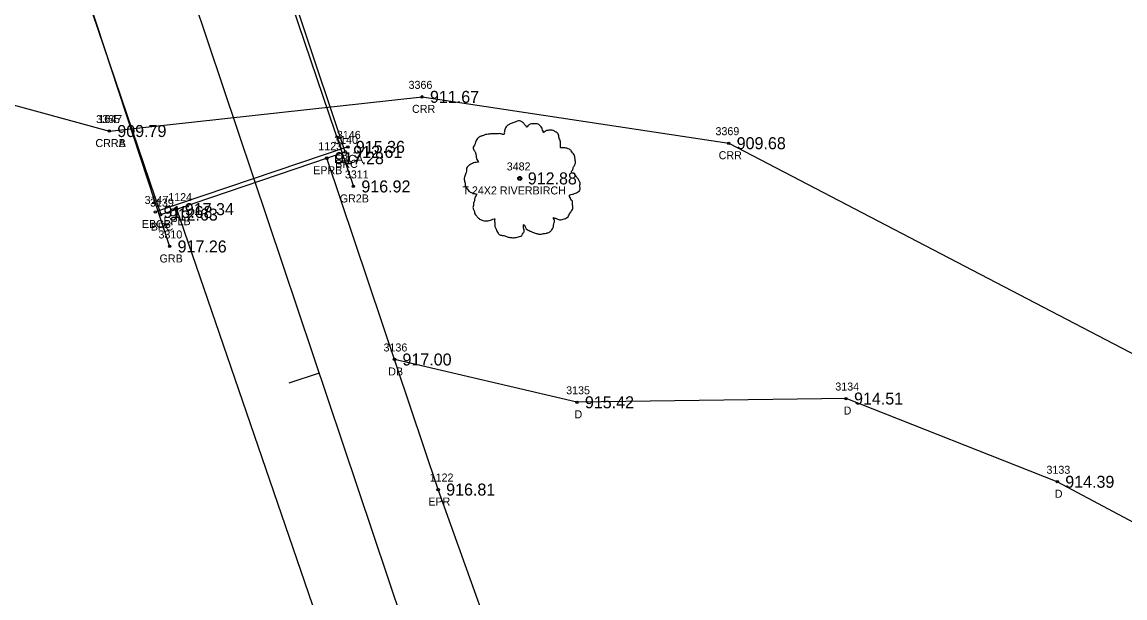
# Model space of a CAD drawing. Extents: x 1528109 to 1531398, y 1157799 to 1162548.
# Drawn here: x 1529638.1 to 1529775.9, y 1160168.9 to 1160240.8 of the extents above; entities that cross this region are included whole.
import ezdxf

# ---------------------------------------------------------------- set-up
doc = ezdxf.new("R2010")
doc.units = 0
for name, color, linetype in [('RD_EX_Bridge', 7, 'Continuous'), ('RD_EX_Bridge_txCode', 7, 'Continuous'), ('RD_EX_Driveway', 7, 'Continuous'), ('RD_EX_Driveway_txCode', 7, 'Continuous'), ('RD_EX_GuardRail', 7, 'Continuous'), ('RD_EX_GuardRail_txCode', 7, 'Continuous'), ('RD_EX_H2O', 7, 'Continuous'), ('RD_EX_H2O_txCode', 7, 'Continuous'), ('RD_EX_Road', 7, 'Continuous'), ('RD_EX_Road_txCode', 7, 'Continuous'), ('RD_EX_TX_Bridge_ELEV', 7, 'Continuous'), ('RD_EX_TX_Driveway_ELEV', 7, 'Continuous'), ('RD_EX_TX_GuardRail_ELEV', 7, 'Continuous'), ('RD_EX_TX_H2O_ELEV', 7, 'Continuous'), ('RD_EX_TX_Road_ELEV', 7, 'Continuous'), ('RD_EX_TX_VEG_ELEV', 7, 'Continuous'), ('RD_EX_VEG', 7, 'Continuous'), ('RD_EX_VEG_txCode', 7, 'Continuous'), ('RD_HC_Cl', 7, 'Continuous'), ('RD_HC_Data_Tic', 7, 'Continuous'), ('RD_SMD_Locator', 7, 'Continuous')]:
    doc.layers.add(name, color=color, linetype=linetype)

msp = doc.modelspace()

# ---------------------------------------------------------------- linework, layer by layer
at = {"layer": 'RD_EX_Bridge'}
msp.add_line((1529678.82, 1160225.23), (1529654.77, 1160217.1), dxfattribs=at)
msp.add_lwpolyline([(1529640.55, 1160338.19), (1529616.81, 1160330.27), (1529655.43, 1160216.77), (1529678.49, 1160224.61), (1529640.55, 1160338.19)], dxfattribs=at)
at = {"layer": 'RD_EX_Driveway'}
msp.add_lwpolyline([(1529846.69, 1160141.22), (1529808.38, 1160161.6), (1529767.49, 1160183.39), (1529741.09, 1160193.79), (1529707.45, 1160193.32), (1529684.65, 1160198.67)], dxfattribs=at)
at = {"layer": 'RD_EX_GuardRail'}
for points in [[(1529639.21, 1160341.22), (1529658.79, 1160281.43), (1529679.51, 1160220.29)], [(1529616.58, 1160333.92), (1529636.5, 1160273.84), (1529656.54, 1160212.79)]]:
    msp.add_lwpolyline(points, dxfattribs=at)
at = {"layer": 'RD_EX_H2O'}
for points in [[(1529355.46, 1160373.84), (1529380.28, 1160350.91), (1529399.96, 1160333.39), (1529434.31, 1160284.33), (1529465.42, 1160247.15), (1529516.1, 1160225.51), (1529574.64, 1160230.43), (1529629.96, 1160232.41), (1529649.01, 1160227.21)], [(1529649.01, 1160227.21), (1529688.09, 1160231.48), (1529726.42, 1160225.69), (1529778.48, 1160198.58), (1529816.5, 1160172.95), (1529890.76, 1160164.82), (1530012.06, 1160143.92), (1530047.21, 1160111.79), (1530065, 1160080.23), (1530106.89, 1160040.72)]]:
    msp.add_lwpolyline(points, dxfattribs=at)
at = {"layer": 'RD_EX_Road'}
for points in [[(1529774.72, 1159933.62), (1529755.68, 1159989.25), (1529731.24, 1160061.98), (1529709.49, 1160126.43), (1529696.87, 1160163.6), (1529690.11, 1160182.42), (1529676.19, 1160223.82)], [(1529755.29, 1159927.01), (1529736.93, 1159982.35), (1529712.51, 1160054.89), (1529690.79, 1160119.37), (1529677.8, 1160158.1), (1529657.44, 1160217.45)]]:
    msp.add_lwpolyline(points, dxfattribs=at)
at = {"layer": 'RD_EX_VEG'}
for centre, radius in [((1529700.31, 1160221.29), 0.25), ((1529700.3, 1160221.27), 0.0001)]:
    msp.add_circle(centre, radius, dxfattribs=at)
for points in [[(1529700.44, 1160228.46), (1529700.14, 1160228.48), (1529699.82, 1160228.38), (1529699.57, 1160228.28), (1529699.34, 1160228.21), (1529699.12, 1160228.11), (1529698.82, 1160227.93), (1529698.59, 1160227.73), (1529698.47, 1160227.48), (1529698.42, 1160227.26), (1529698.37, 1160226.98), (1529698.37, 1160226.81), (1529698.24, 1160226.78), (1529698.09, 1160226.81), (1529697.84, 1160226.88), (1529697.59, 1160226.88), (1529697.34, 1160226.88), (1529696.99, 1160226.86), (1529696.64, 1160226.86), (1529696.37, 1160226.81), (1529696.04, 1160226.76), (1529695.67, 1160226.63), (1529695.32, 1160226.51), (1529695.02, 1160226.26), (1529694.77, 1160225.78), (1529694.64, 1160225.43), (1529694.49, 1160225.18), (1529694.64, 1160224.73), (1529694.82, 1160224.38), (1529694.84, 1160224.18), (1529694.92, 1160223.76), (1529695.02, 1160223.53), (1529695.14, 1160223.33), (1529695.07, 1160223.31), (1529694.69, 1160223.26), (1529694.39, 1160223.16), (1529693.97, 1160222.93), (1529693.74, 1160222.71), (1529693.64, 1160222.38), (1529693.62, 1160222.04), (1529693.52, 1160221.84), (1529693.45, 1160221.56), (1529693.42, 1160221.49), (1529693.37, 1160221.16), (1529693.47, 1160220.71), (1529693.5, 1160220.36), (1529693.62, 1160220.14), (1529693.77, 1160219.96), (1529693.94, 1160219.71), (1529694.34, 1160219.49), (1529694.67, 1160219.39), (1529694.87, 1160219.36), (1529694.69, 1160218.86), (1529694.64, 1160218.51), (1529694.52, 1160218.11), (1529694.52, 1160218.04), (1529694.47, 1160217.56), (1529694.62, 1160217.24), (1529694.69, 1160216.86), (1529694.87, 1160216.64), (1529695.14, 1160216.34), (1529695.47, 1160216.11), (1529695.97, 1160215.99), (1529696.37, 1160216.01), (1529696.94, 1160216.19), (1529697.19, 1160216.26), (1529697.17, 1160216.09), (1529697.19, 1160215.71), (1529697.19, 1160215.29), (1529697.34, 1160214.96), (1529697.44, 1160214.69), (1529697.59, 1160214.44), (1529697.92, 1160214.21), (1529698.32, 1160214.14), (1529698.74, 1160213.99), (1529699.19, 1160213.91), (1529699.69, 1160213.89), (1529700.29, 1160214.04), (1529700.57, 1160214.16), (1529700.67, 1160214.34), (1529700.87, 1160214.71), (1529700.82, 1160214.94), (1529700.84, 1160215.54), (1529700.94, 1160215.36), (1529701.12, 1160215.01), (1529701.62, 1160214.71), (1529702.02, 1160214.54), (1529702.49, 1160214.39), (1529702.79, 1160214.31), (1529703.27, 1160214.39), (1529703.64, 1160214.46), (1529704.02, 1160214.59), (1529704.32, 1160214.86), (1529704.49, 1160215.14), (1529704.54, 1160215.41), (1529704.62, 1160215.79), (1529704.67, 1160215.96)], [(1529704.67, 1160215.96), (1529704.59, 1160216.14), (1529704.54, 1160216.39), (1529704.62, 1160216.36), (1529704.79, 1160216.31), (1529705.06, 1160216.19), (1529705.29, 1160216.11), (1529705.61, 1160216.14), (1529705.89, 1160216.24), (1529706.34, 1160216.51), (1529706.61, 1160216.99), (1529706.89, 1160217.39), (1529706.96, 1160217.71), (1529706.91, 1160217.94), (1529706.89, 1160218.44), (1529706.69, 1160218.69), (1529706.64, 1160218.81), (1529706.54, 1160219.21), (1529706.61, 1160219.26), (1529706.89, 1160219.31), (1529707.26, 1160219.44), (1529707.54, 1160219.56), (1529707.76, 1160219.74), (1529707.84, 1160219.96), (1529707.81, 1160220.36), (1529707.86, 1160220.76), (1529707.79, 1160220.91), (1529707.69, 1160221.06), (1529707.61, 1160221.26), (1529707.46, 1160221.41), (1529707.36, 1160221.56), (1529707.26, 1160221.66), (1529707.14, 1160221.81), (1529706.96, 1160221.94), (1529706.81, 1160221.99), (1529706.76, 1160222.14), (1529706.91, 1160222.33), (1529706.96, 1160222.43), (1529706.99, 1160222.66), (1529707.21, 1160223.01), (1529707.26, 1160223.41), (1529707.21, 1160223.83), (1529707.16, 1160224.11), (1529707.01, 1160224.38), (1529706.81, 1160224.63), (1529706.69, 1160224.81), (1529706.51, 1160224.93), (1529706.19, 1160225.06), (1529705.94, 1160225.11), (1529705.59, 1160225.11), (1529705.39, 1160225.16), (1529705.41, 1160225.21), (1529705.41, 1160225.36), (1529705.41, 1160225.63), (1529705.34, 1160226.08), (1529705.19, 1160226.58), (1529705.19, 1160226.61), (1529705.09, 1160226.86), (1529704.87, 1160227.06), (1529704.69, 1160227.16), (1529704.49, 1160227.28), (1529704.24, 1160227.31), (1529703.94, 1160227.31), (1529703.67, 1160227.26), (1529703.47, 1160227.16), (1529703.29, 1160227.03), (1529703.22, 1160227.18), (1529703.12, 1160227.48), (1529703.07, 1160227.63), (1529702.92, 1160227.81), (1529702.69, 1160228.01), (1529702.24, 1160228.13), (1529701.62, 1160228.06), (1529701.32, 1160227.86), (1529701.17, 1160227.68), (1529701.12, 1160227.81), (1529700.92, 1160228.01), (1529700.82, 1160228.18), (1529700.64, 1160228.31), (1529700.49, 1160228.41), (1529700.39, 1160228.46)]]:
    msp.add_spline(points, degree=3, dxfattribs=at)
at = {"layer": 'RD_HC_Cl'}
msp.add_line((1529913.5, 1159487.74), (1529527.85, 1160635.77), dxfattribs=at)
at = {"layer": 'RD_HC_Data_Tic'}
msp.add_line((1529675.25, 1160196.97), (1529671.46, 1160195.7), dxfattribs=at)
at = {"layer": 'RD_SMD_Locator'}
for centre in [(1529688.09, 1160231.48), (1529649.01, 1160227.21), (1529649.01, 1160227.21), (1529678.49, 1160224.61), (1529678.82, 1160225.23), (1529726.42, 1160225.69), (1529676.19, 1160223.82), (1529700.31, 1160221.29), (1529679.51, 1160220.29), (1529654.77, 1160217.1), (1529655.43, 1160216.77), (1529657.44, 1160217.45), (1529656.54, 1160212.79), (1529684.65, 1160198.67), (1529707.45, 1160193.32), (1529741.09, 1160193.79), (1529767.49, 1160183.39), (1529690.11, 1160182.42)]:
    msp.add_circle(centre, 0.15, dxfattribs=at)

# ---------------------------------------------------------------- texts
at = {"layer": 'RD_EX_Bridge_txCode'}
for s, p in [('3140', (1529677.11, 1160225.61)), ('3146', (1529677.45, 1160226.23)), ('EBCA', (1529677.1, 1160223.23)), ('BRC', (1529677.24, 1160222.61)), ('3147', (1529653.42, 1160218.1)), ('3139', (1529654.09, 1160217.77)), ('EBCB', (1529653.07, 1160215.1)), ('BRC', (1529654.18, 1160214.77))]:
    msp.add_text(s, height=1, dxfattribs=at).set_placement(p)
at = {"layer": 'RD_EX_Driveway_txCode'}
for s, p in [('3136', (1529683.28, 1160199.67)), ('DB', (1529683.87, 1160196.67)), ('3134', (1529739.75, 1160194.79)), ('3135', (1529706.11, 1160194.32)), ('D', (1529707.15, 1160191.32)), ('D', (1529740.79, 1160191.79)), ('3133', (1529766.14, 1160184.39)), ('D', (1529767.18, 1160181.39))]:
    msp.add_text(s, height=1, dxfattribs=at).set_placement(p)
at = {"layer": 'RD_EX_GuardRail_txCode'}
for s, p in [('3311', (1529678.45, 1160221.29)), ('GR2B', (1529677.81, 1160218.29)), ('3310', (1529655.15, 1160213.79)), ('GRB', (1529655.29, 1160210.79))]:
    msp.add_text(s, height=1, dxfattribs=at).set_placement(p)
at = {"layer": 'RD_EX_H2O_txCode'}
for s, p in [('3366', (1529686.41, 1160232.48)), ('CRR', (1529686.84, 1160229.48)), ('3365', (1529647.36, 1160228.21)), ('1647', (1529647.64, 1160228.21)), ('3369', (1529724.77, 1160226.69)), ('CRRA', (1529647.27, 1160225.21)), ('CRRB', (1529647.28, 1160225.21)), ('CRR', (1529725.17, 1160223.69))]:
    msp.add_text(s, height=1, dxfattribs=at).set_placement(p)
at = {"layer": 'RD_EX_Road_txCode'}
for s, p in [('1123', (1529675.13, 1160224.82)), ('EPRB', (1529674.49, 1160221.82)), ('1124', (1529656.37, 1160218.45)), ('EPLB', (1529655.76, 1160215.45)), ('1122', (1529689.05, 1160183.42)), ('EPR', (1529688.88, 1160180.42))]:
    msp.add_text(s, height=1, dxfattribs=at).set_placement(p)
at = {"layer": 'RD_EX_TX_Bridge_ELEV'}
for s, p in [('912.61', (1529679.49, 1160223.86)), ('915.36', (1529679.82, 1160224.48)), ('915.68', (1529655.77, 1160216.35)), ('912.63', (1529656.43, 1160216.02))]:
    msp.add_text(s, height=1.5, dxfattribs=at).set_placement(p)
at = {"layer": 'RD_EX_TX_Driveway_ELEV'}
for s, p in [('917.00', (1529685.65, 1160197.92)), ('914.51', (1529742.09, 1160193.04)), ('915.42', (1529708.45, 1160192.57)), ('914.39', (1529768.49, 1160182.64))]:
    msp.add_text(s, height=1.5, dxfattribs=at).set_placement(p)
at = {"layer": 'RD_EX_TX_GuardRail_ELEV'}
for s, p in [('916.92', (1529680.51, 1160219.54)), ('917.26', (1529657.54, 1160212.04))]:
    msp.add_text(s, height=1.5, dxfattribs=at).set_placement(p)
at = {"layer": 'RD_EX_TX_H2O_ELEV'}
for s, p in [('911.67', (1529689.09, 1160230.73)), ('909.79', (1529650.01, 1160226.46)), ('909.79', (1529650.01, 1160226.46)), ('909.68', (1529727.42, 1160224.94))]:
    msp.add_text(s, height=1.5, dxfattribs=at).set_placement(p)
at = {"layer": 'RD_EX_TX_Road_ELEV'}
for s, p in [('917.28', (1529677.19, 1160223.07)), ('917.34', (1529658.44, 1160216.7)), ('916.81', (1529691.11, 1160181.67))]:
    msp.add_text(s, height=1.5, dxfattribs=at).set_placement(p)
at = {"layer": 'RD_EX_TX_VEG_ELEV'}
msp.add_text('912.88', height=1.5, dxfattribs=at).set_placement((1529701.31, 1160220.54))
at = {"layer": 'RD_EX_VEG_txCode'}
for s, p in [('3482', (1529698.68, 1160222.29)), ('T 24X2 RIVERBIRCH', (1529693.14, 1160219.29))]:
    msp.add_text(s, height=1, dxfattribs=at).set_placement(p)

doc.saveas('drawing.dxf')
